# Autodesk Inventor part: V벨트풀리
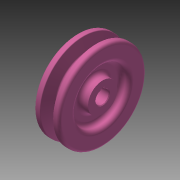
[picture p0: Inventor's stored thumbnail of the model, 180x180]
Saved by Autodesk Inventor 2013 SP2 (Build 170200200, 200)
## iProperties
Created: 2015-11
Part Number: V벨트풀리
Material: 강철, 탄소
Document SubType Name: Modeling
Designer: mduedu
Density: 1 g/cm^3
Author: mduedu
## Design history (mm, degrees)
sketch "스케치1"
  geometry: L1 (-9.5, 0)-(9.5, 0); L2 (0, 0)-(0, 32.7); L3 (-4.825, 32.7)-(-9.5, 32.7); L4 (-9.5, 32.7)-(-9.5, 0); L5 (0, 23.7)-(-2.074, 23.7); L6 (-2.074, 23.7)-(-4.825, 32.7); L7 (4.825, 32.7)-(9.5, 32.7); L8 (9.5, 32.7)-(9.5, 0); L9 (0, 23.7)-(2.074, 23.7); L10 (2.074, 23.7)-(4.825, 32.7); L11 (-9.5, 30)-(9.5, 30); 3 further points
  constraints: 22 end point, 7 point on line, 4 perpendicular, 3 symmetric about line, 1 coincident, 1 horizontal, 1 horizontal alignment, 1 midpoint, 1 vertical
  dimensions: "d0" = 19 distance of L1.start L1.end; "d2" = 65.4 diameter of L2.end L1 (derived); "d3" = 34 deg angle of L10 L6; "d4" = 6.3 distance between parallel lines of L11 L9; "d5" = 2.7 distance between parallel lines of L7 L11; "d6" = 8 distance of point (4, 30) point (-4, 30); "d7" = 60 diameter of L11 L1
revolve "회전1" sketch "스케치1" stored, may be unused: angle "d8" = 90 deg
sketch "스케치2"
  geometry: C1 r 20 at (0, 0); C2 r 11 at (0, 0); 1 further point
  constraints: 2 centre point, 2 coincident
  dimensions: "d9" = 40 diameter of C1; "d10" = 22 diameter of C2
extrude "돌출1" cut sketch "스케치2" distance "d11" = 6; taper "d12" = 0 deg
fillet "모깎기1" dims "d13" = 3
fillet "모깎기2" dims "d14" = 3
fillet "모깎기3" dims "d15" = 1, "d16" = 0.5, "d17" = 2
hole "구멍1" diameter "d20" = 10; stored, may be unused: countersink angle "d24" = 90 deg, drill point angle "d26" = 118 deg; dims "d18" = 10, "d19" = 10, "d21" = 6, "d22" = 4, "d23" = 2, "d25" = 8
sketch "스케치3"
  geometry: L1 (-1.5, 0)-(1.5, 0); L2 (1.5, 0)-(1.5, 6.4); L3 (1.5, 6.4)-(-1.5, 6.4); L4 (-1.5, 6.4)-(-1.5, 0); 2 further points
  constraints: 8 end point, 2 parallel, 1 coincident, 1 horizontal, 1 midpoint, 1 perpendicular
  dimensions: "d27" = 3 distance of L2.end L3.end; "d29" = 6.4 distance of L3.end L1.start
extrude "돌출2" cut sketch "스케치3" stored distance "d30" = 6; taper "d31" = 0 deg
chamfer "모따기1" distance "d32" = 0.5; stored, may be unused: second distance "d33" = 2, angle "d34" = 45 deg
node "솔리드1"
mirror "대칭1"
